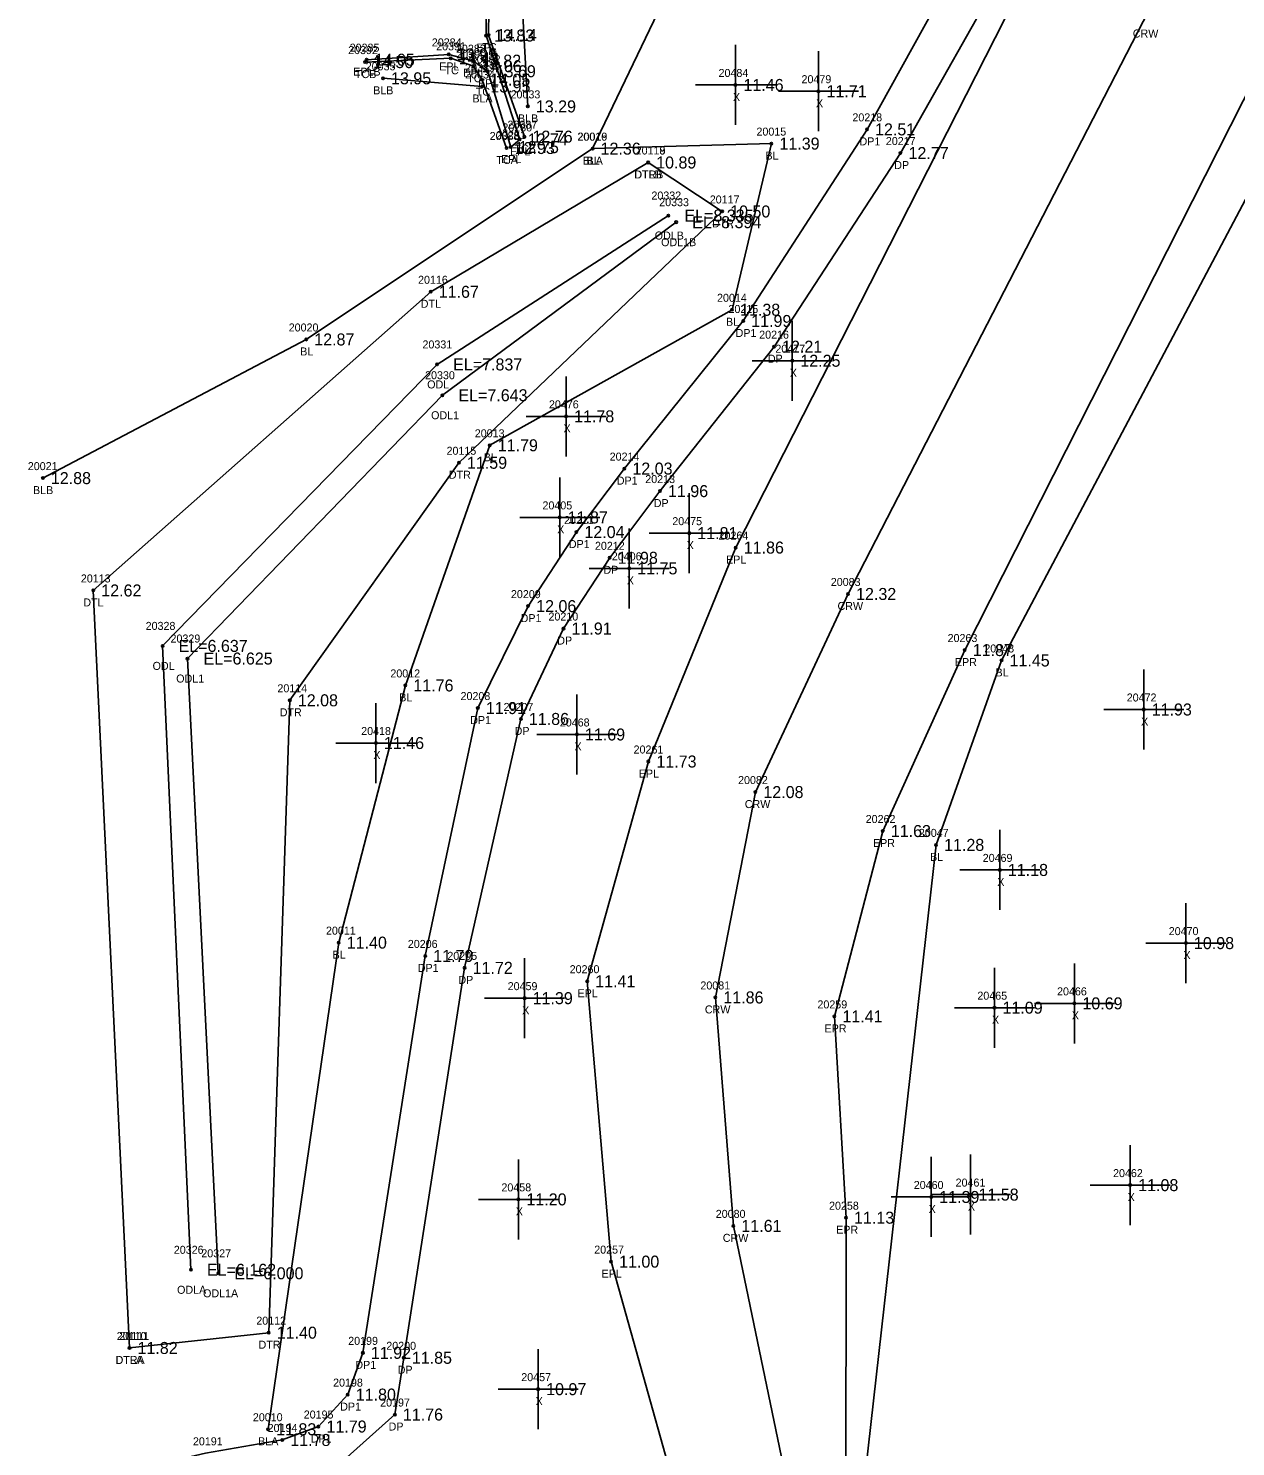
# Model space of a CAD drawing. Extents: x 2072302 to 2072980, y 127650 to 129736.
# Drawn here: x 2072687.3 to 2072838.2, y 128354.3 to 128531.6 of the extents above; entities that cross this region are included whole.
import ezdxf

# ---------------------------------------------------------------- set-up
doc = ezdxf.new("R2010")
doc.units = 0
for name, color, linetype in [('RD_DTM_BkLn1', 7, 'Continuous'), ('RD_DTM_BkLn2', 7, 'Continuous'), ('RD_DTM_BkLn_txCode', 7, 'Continuous'), ('RD_EX_Conc_txCode', 7, 'Continuous'), ('RD_EX_Driveway', 7, 'Continuous'), ('RD_EX_Driveway_txCode', 7, 'Continuous'), ('RD_EX_H2O', 7, 'Continuous'), ('RD_EX_H2O_txCode', 7, 'Continuous'), ('RD_EX_Misc', 7, 'Continuous'), ('RD_EX_Misc_txCode', 7, 'Continuous'), ('RD_EX_Road', 7, 'Continuous'), ('RD_EX_Road_txCode', 7, 'Continuous'), ('RD_EX_TX_Conc_ELEV', 7, 'Continuous'), ('RD_EX_TX_Driveway_ELEV', 7, 'Continuous'), ('RD_EX_TX_H2O_ELEV', 7, 'Continuous'), ('RD_EX_TX_Misc_ELEV', 7, 'Continuous'), ('RD_EX_TX_Road_ELEV', 7, 'Continuous'), ('RD_HC_Survey_ELEV', 7, 'Continuous'), ('RD_HC_Survey_txCode', 7, 'Continuous'), ('RD_SMD_Locator', 7, 'Continuous')]:
    doc.layers.add(name, color=color, linetype=linetype)

msp = doc.modelspace()

# ---------------------------------------------------------------- linework, layer by layer
at = {"layer": 'RD_DTM_BkLn1'}
for p, q in [((2072748.82, 128537.75), (2072749.69, 128521.83)), ((2072744, 128524.32), (2072731.59, 128525.34))]:
    msp.add_line(p, q, dxfattribs=at)
for points in [[(2072783.68, 128341.98), (2072775.38, 128381.91), (2072773.13, 128410.46), (2072778.13, 128436.13), (2072789.72, 128460.89), (2072826.62, 128532.44), (2072863.13, 128603.15), (2072886.77, 128648.23), (2072893.1, 128661.91)], [(2072717.23, 128356.49), (2072726.05, 128417.31), (2072734.38, 128449.46), (2072744.93, 128479.47), (2072775.22, 128496.41), (2072780.14, 128517.18), (2072757.78, 128516.55), (2072777.16, 128556.96), (2072786.53, 128575.88)], [(2072791.29, 128345.62), (2072800.72, 128429.53), (2072808.9, 128452.58), (2072870.32, 128568.64), (2072876.57, 128573.6), (2072916.77, 128564.68), (2072920.97, 128548.67)], [(2072757.78, 128516.55), (2072721.99, 128492.7), (2072689.07, 128475.37)]]:
    msp.add_lwpolyline(points, dxfattribs=at)
at = {"layer": 'RD_DTM_BkLn2'}
for points in [[(2072745.36, 128575.1), (2072744.79, 128530.75), (2072749.27, 128518.05)], [(2072747.04, 128516.63), (2072743.97, 128525.17), (2072742.91, 128526.85), (2072740.06, 128527.84), (2072729.35, 128527.37)]]:
    msp.add_lwpolyline(points, dxfattribs=at)
at = {"layer": 'RD_EX_Driveway'}
for points in [[(2072694.21, 128239.74), (2072695.7, 128289.15), (2072695.56, 128330.43), (2072696.37, 128337.85), (2072700.81, 128345.17), (2072711.22, 128347.96), (2072719.56, 128349.59), (2072725.15, 128351.26), (2072733.07, 128358.33), (2072734.19, 128365.42), (2072741.79, 128414.16), (2072748.82, 128445.27), (2072754.15, 128456.57), (2072759.92, 128465.41), (2072766.21, 128473.75), (2072780.47, 128491.8), (2072796.27, 128516), (2072809.9, 128540.1), (2072821.01, 128555.78)], [(2072689.37, 128239.9), (2072690.93, 128289.43), (2072690.32, 128330.24), (2072690.73, 128338.81), (2072697.63, 128350.77), (2072709.38, 128353.48), (2072719, 128355.15), (2072723.52, 128356.83), (2072727.18, 128360.82), (2072729.07, 128366.04), (2072736.87, 128415.65), (2072743.44, 128446.63), (2072749.73, 128459.37), (2072755.76, 128468.63), (2072761.76, 128476.56), (2072776.61, 128495.01), (2072792.09, 128518.96), (2072805.19, 128542.59), (2072810.66, 128554.44), (2072797.46, 128551.01)]]:
    msp.add_lwpolyline(points, dxfattribs=at)
at = {"layer": 'RD_EX_H2O'}
for points in [[(2072699.9, 128366.65), (2072695.37, 128461.33), (2072737.55, 128498.66), (2072764.73, 128514.82)], [(2072699.9, 128366.65), (2072717.3, 128368.56), (2072719.94, 128447.6), (2072741.08, 128477.29), (2072773.98, 128508.7), (2072764.73, 128514.82)], [(2072707.58, 128376.42), (2072704.03, 128454.4), (2072738.35, 128489.58), (2072767.26, 128508.19)], [(2072711, 128375.98), (2072707.15, 128452.82), (2072739.01, 128485.73), (2072768.23, 128507.36)]]:
    msp.add_lwpolyline(points, dxfattribs=at)
at = {"layer": 'RD_EX_Misc'}
for p, q in [((2072775.64, 128519.51), (2072775.64, 128529.51)), ((2072786.02, 128518.73), (2072786.02, 128528.73)), ((2072770.64, 128524.51), (2072780.64, 128524.51)), ((2072781.02, 128523.73), (2072791.02, 128523.73)), ((2072782.75, 128485.04), (2072782.75, 128495.04)), ((2072777.75, 128490.04), (2072787.75, 128490.04)), ((2072754.47, 128478.09), (2072754.47, 128488.09)), ((2072749.47, 128483.09), (2072759.47, 128483.09)), ((2072753.67, 128465.46), (2072753.67, 128475.46)), ((2072769.87, 128463.49), (2072769.87, 128473.49)), ((2072748.67, 128470.46), (2072758.67, 128470.46)), ((2072762.37, 128459.09), (2072762.37, 128469.09)), ((2072764.87, 128468.49), (2072774.87, 128468.49)), ((2072757.37, 128464.09), (2072767.37, 128464.09)), ((2072826.67, 128441.45), (2072826.67, 128451.45)), ((2072755.83, 128438.33), (2072755.83, 128448.33)), ((2072730.7, 128437.26), (2072730.7, 128447.26)), ((2072821.67, 128446.45), (2072831.67, 128446.45)), ((2072750.83, 128443.33), (2072760.83, 128443.33)), ((2072725.7, 128442.26), (2072735.7, 128442.26)), ((2072808.69, 128421.4), (2072808.69, 128431.4)), ((2072803.69, 128426.4), (2072813.69, 128426.4)), ((2072831.95, 128412.25), (2072831.95, 128422.25)), ((2072826.95, 128417.25), (2072836.95, 128417.25)), ((2072749.29, 128405.37), (2072749.29, 128415.37)), ((2072818.01, 128404.72), (2072818.01, 128414.72)), ((2072808.02, 128404.18), (2072808.02, 128414.18)), ((2072744.29, 128410.37), (2072754.29, 128410.37)), ((2072803.02, 128409.18), (2072813.02, 128409.18)), ((2072813.01, 128409.72), (2072823.01, 128409.72)), ((2072824.98, 128382), (2072824.98, 128392)), ((2072748.51, 128380.22), (2072748.51, 128390.22)), ((2072800.11, 128380.52), (2072800.11, 128390.52)), ((2072805.02, 128380.82), (2072805.02, 128390.82)), ((2072819.98, 128387), (2072829.98, 128387)), ((2072743.51, 128385.22), (2072753.51, 128385.22)), ((2072795.11, 128385.52), (2072805.11, 128385.52)), ((2072800.02, 128385.82), (2072810.02, 128385.82)), ((2072750.98, 128356.5), (2072750.98, 128366.5)), ((2072745.98, 128361.5), (2072755.98, 128361.5))]:
    msp.add_line(p, q, dxfattribs=at)
at = {"layer": 'RD_EX_Road'}
for points in [[(2072789.45, 128345.69), (2072789.46, 128382.93), (2072788.01, 128408.09), (2072794.06, 128431.26), (2072804.3, 128453.88), (2072840.7, 128525.64), (2072876.68, 128596.08), (2072888.72, 128617.36), (2072893.24, 128622.62), (2072899.84, 128627.36), (2072910.72, 128631.76), (2072918.79, 128632.23), (2072935.82, 128627.02), (2072957.37, 128619.98)], [(2072744.65, 128575.04), (2072744.47, 128530.69), (2072748.67, 128517.7), (2072747.55, 128516.74), (2072744.67, 128526.22), (2072742.83, 128527.54), (2072739.81, 128528.33), (2072729.54, 128527.67)], [(2072771.5, 128336.87), (2072760.1, 128377.44), (2072757.11, 128412.49), (2072764.76, 128439.95), (2072775.68, 128466.69), (2072812.91, 128539.86)]]:
    msp.add_lwpolyline(points, dxfattribs=at)
at = {"layer": 'RD_SMD_Locator'}
for centre in [(2072744.47, 128530.69), (2072744.79, 128530.75), (2072739.81, 128528.33), (2072740.06, 128527.84), (2072729.35, 128527.37), (2072729.54, 128527.67), (2072742.83, 128527.54), (2072742.91, 128526.85), (2072744.67, 128526.22), (2072731.59, 128525.34), (2072743.97, 128525.17), (2072744, 128524.32), (2072775.64, 128524.51), (2072786.02, 128523.73), (2072749.69, 128521.83), (2072792.09, 128518.96), (2072748.67, 128517.7), (2072749.27, 128518.05), (2072780.14, 128517.18), (2072747.04, 128516.63), (2072747.55, 128516.74), (2072757.78, 128516.55), (2072757.78, 128516.55), (2072796.27, 128516), (2072764.73, 128514.82), (2072764.73, 128514.82), (2072773.98, 128508.7), (2072767.26, 128508.19), (2072768.23, 128507.36), (2072737.55, 128498.66), (2072775.22, 128496.41), (2072776.61, 128495.01), (2072721.99, 128492.7), (2072780.47, 128491.8), (2072738.35, 128489.58), (2072782.75, 128490.04), (2072739.01, 128485.73), (2072754.47, 128483.09), (2072744.93, 128479.47), (2072741.08, 128477.29), (2072761.76, 128476.56), (2072689.07, 128475.37), (2072766.21, 128473.75), (2072753.67, 128470.46), (2072755.76, 128468.63), (2072769.87, 128468.49), (2072775.68, 128466.69), (2072759.92, 128465.41), (2072762.37, 128464.09), (2072695.37, 128461.33), (2072789.72, 128460.89), (2072749.73, 128459.37), (2072754.15, 128456.57), (2072704.03, 128454.4), (2072804.3, 128453.88), (2072707.15, 128452.82), (2072808.9, 128452.58), (2072734.38, 128449.46), (2072719.94, 128447.6), (2072743.44, 128446.63), (2072826.67, 128446.45), (2072748.82, 128445.27), (2072755.83, 128443.33), (2072730.7, 128442.26), (2072764.76, 128439.95), (2072778.13, 128436.13), (2072794.06, 128431.26), (2072800.72, 128429.53), (2072808.69, 128426.4), (2072726.05, 128417.31), (2072831.95, 128417.25), (2072736.87, 128415.65), (2072741.79, 128414.16), (2072757.11, 128412.49), (2072749.29, 128410.37), (2072773.13, 128410.46), (2072808.02, 128409.18), (2072818.01, 128409.72), (2072788.01, 128408.09), (2072824.98, 128387), (2072748.51, 128385.22), (2072800.11, 128385.52), (2072805.02, 128385.82), (2072789.46, 128382.93), (2072775.38, 128381.91), (2072760.1, 128377.44), (2072707.58, 128376.42), (2072711, 128375.98), (2072717.3, 128368.56), (2072699.9, 128366.65), (2072699.9, 128366.65), (2072729.07, 128366.04), (2072734.19, 128365.42), (2072750.98, 128361.5), (2072727.18, 128360.82), (2072733.07, 128358.33), (2072717.23, 128356.49), (2072723.52, 128356.83), (2072719, 128355.15)]:
    msp.add_circle(centre, 0.15, dxfattribs=at)

# ---------------------------------------------------------------- texts
at = {"layer": 'RD_DTM_BkLn_txCode'}
for s, p in [('20035', (2072729.43, 128526.34)), ('20034', (2072741.84, 128525.32)), ('BLB', (2072730.36, 128523.34)), ('BLA', (2072742.76, 128522.32)), ('20033', (2072747.53, 128522.83)), ('BLB', (2072748.46, 128519.83)), ('20015', (2072778.27, 128518.18)), ('20016', (2072755.88, 128517.55)), ('20019', (2072755.91, 128517.55)), ('BLA', (2072756.54, 128514.55)), ('BL', (2072757.03, 128514.55)), ('BL', (2072779.39, 128515.18)), ('20014', (2072773.34, 128497.41)), ('20020', (2072719.8, 128493.7)), ('BL', (2072774.46, 128494.41)), ('BL', (2072721.24, 128490.7)), ('20013', (2072743.06, 128480.47)), ('BL', (2072744.18, 128477.47)), ('20021', (2072687.19, 128476.37)), ('BLB', (2072687.84, 128473.37)), ('20048', (2072806.75, 128453.58)), ('20012', (2072732.51, 128450.46)), ('BL', (2072808.15, 128450.58)), ('BL', (2072733.62, 128447.46)), ('20047', (2072798.57, 128430.53)), ('BL', (2072799.97, 128427.53)), ('20011', (2072724.46, 128418.31)), ('BL', (2072725.29, 128415.31)), ('20010', (2072715.32, 128357.49)), ('BLA', (2072715.98, 128354.49))]:
    msp.add_text(s, height=1, dxfattribs=at).set_placement(p)
at = {"layer": 'RD_EX_Conc_txCode'}
for s, p in [('20391', (2072738.23, 128528.84)), ('TC', (2072744, 128528.75)), ('20392', (2072727.23, 128528.37)), ('20390', (2072740.75, 128527.85)), ('TCB', (2072728.08, 128525.37)), ('TC', (2072739.27, 128525.84)), ('20389', (2072741.85, 128526.17)), ('TC', (2072742.11, 128524.85)), ('TC', (2072743.18, 128523.17)), ('20387', (2072747.15, 128519.05)), ('20388', (2072744.92, 128517.63)), ('TCA', (2072745.76, 128514.63)), ('TCB', (2072748.01, 128516.05))]:
    msp.add_text(s, height=1, dxfattribs=at).set_placement(p)
at = {"layer": 'RD_EX_Driveway_txCode'}
for s, p in [('20218', (2072790.26, 128519.96)), ('DP1', (2072791.15, 128516.96)), ('20217', (2072794.44, 128517)), ('DP', (2072795.49, 128514)), ('20215', (2072774.77, 128496.01)), ('DP1', (2072775.66, 128493.01)), ('20216', (2072778.61, 128492.8)), ('DP', (2072779.69, 128489.8)), ('20214', (2072759.92, 128477.56)), ('DP1', (2072760.81, 128474.56)), ('20213', (2072764.37, 128474.75)), ('DP', (2072765.43, 128471.75)), ('20211', (2072754.21, 128469.63)), ('DP1', (2072754.82, 128466.63)), ('20212', (2072758.08, 128466.41)), ('DP', (2072759.14, 128463.41)), ('20209', (2072747.58, 128460.37)), ('DP1', (2072748.79, 128457.37)), ('20210', (2072752.27, 128457.57)), ('DP', (2072753.37, 128454.57)), ('20208', (2072741.28, 128447.63)), ('20207', (2072746.66, 128446.27)), ('DP1', (2072742.49, 128444.63)), ('DP', (2072748.04, 128443.27)), ('20206', (2072734.69, 128416.65)), ('DP1', (2072735.93, 128413.65)), ('20205', (2072739.63, 128415.16)), ('DP', (2072741.01, 128412.16)), ('20199', (2072727.24, 128367.04)), ('20200', (2072732, 128366.42)), ('DP1', (2072728.13, 128364.04)), ('DP', (2072733.42, 128363.42)), ('20198', (2072725.35, 128361.82)), ('DP1', (2072726.24, 128358.82)), ('20197', (2072731.23, 128359.33)), ('20195', (2072721.68, 128357.83)), ('20194', (2072717.17, 128356.15)), ('DP', (2072732.29, 128356.33)), ('20191', (2072707.83, 128354.48)), ('DP1', (2072722.57, 128354.83))]:
    msp.add_text(s, height=1, dxfattribs=at).set_placement(p)
at = {"layer": 'RD_EX_H2O_txCode'}
for s, p in [('20118', (2072763.17, 128515.82)), ('20119', (2072763.17, 128515.82)), ('DTRB', (2072762.98, 128512.82)), ('DTLB', (2072763.01, 128512.82)), ('20332', (2072765.14, 128510.19)), ('20333', (2072766.11, 128509.36)), ('20117', (2072772.43, 128509.7)), ('DTR', (2072772.71, 128506.7)), ('ODLB', (2072765.55, 128505.19)), ('ODL1B', (2072766.35, 128504.36)), ('20116', (2072735.97, 128499.66)), ('DTL', (2072736.3, 128496.66)), ('20331', (2072736.52, 128491.58)), ('20330', (2072736.85, 128487.73)), ('ODL', (2072737.11, 128486.58)), ('ODL1', (2072737.6, 128482.73)), ('20115', (2072739.53, 128478.29)), ('DTR', (2072739.82, 128475.29)), ('20113', (2072693.82, 128462.33)), ('DTL', (2072694.13, 128459.33)), ('20328', (2072701.92, 128456.4)), ('20329', (2072705.03, 128454.82)), ('ODL', (2072702.79, 128451.4)), ('ODL1', (2072705.74, 128449.82)), ('20114', (2072718.39, 128448.6)), ('DTR', (2072718.68, 128445.6)), ('20326', (2072705.44, 128378.42)), ('20327', (2072708.88, 128377.98)), ('ODLA', (2072705.85, 128373.42)), ('ODL1A', (2072709.1, 128372.98)), ('20112', (2072715.75, 128369.56)), ('20110', (2072698.31, 128367.65)), ('20111', (2072698.63, 128367.65)), ('DTR', (2072716.03, 128366.56)), ('DTRA', (2072698.15, 128364.65)), ('DTLA', (2072698.17, 128364.65))]:
    msp.add_text(s, height=1, dxfattribs=at).set_placement(p)
at = {"layer": 'RD_EX_Misc_txCode'}
for s, p in [('20484', (2072773.53, 128525.51)), ('20479', (2072783.9, 128524.73)), ('X', (2072775.33, 128522.51)), ('X', (2072785.71, 128521.73)), ('20477', (2072780.63, 128491.04)), ('X', (2072782.43, 128488.04)), ('20476', (2072752.33, 128484.09)), ('X', (2072754.15, 128481.09)), ('20405', (2072751.52, 128471.46)), ('X', (2072753.36, 128468.46)), ('20475', (2072767.75, 128469.49)), ('20406', (2072760.19, 128465.09)), ('X', (2072769.55, 128466.49)), ('X', (2072762.06, 128462.09)), ('20472', (2072824.55, 128447.45)), ('20468', (2072753.69, 128444.33)), ('X', (2072826.35, 128444.45)), ('20418', (2072728.86, 128443.26)), ('X', (2072730.38, 128440.26)), ('X', (2072755.52, 128441.33)), ('20469', (2072806.55, 128427.4)), ('X', (2072808.37, 128424.4)), ('20470', (2072829.8, 128418.25)), ('X', (2072831.64, 128415.25)), ('20459', (2072747.17, 128411.37)), ('20465', (2072805.88, 128410.18)), ('20466', (2072815.84, 128410.72)), ('X', (2072748.98, 128408.37)), ('X', (2072807.71, 128407.18)), ('X', (2072817.69, 128407.72)), ('20462', (2072822.84, 128388)), ('20458', (2072746.39, 128386.22)), ('20460', (2072797.93, 128386.52)), ('20461', (2072803.16, 128386.82)), ('X', (2072799.79, 128383.52)), ('X', (2072804.7, 128383.82)), ('X', (2072824.67, 128385)), ('X', (2072748.19, 128383.22)), ('20457', (2072748.87, 128362.5)), ('X', (2072750.67, 128359.5))]:
    msp.add_text(s, height=1, dxfattribs=at).set_placement(p)
at = {"layer": 'RD_EX_Road_txCode'}
for s, p in [('20284', (2072737.69, 128529.33)), ('20285', (2072727.42, 128528.67)), ('20283', (2072740.71, 128528.54)), ('20282', (2072742.56, 128527.22)), ('EPL', (2072743.26, 128528.69)), ('EPLB', (2072727.86, 128525.67)), ('EPL', (2072738.61, 128526.33)), ('EPL', (2072741.62, 128525.54)), ('EPL', (2072743.47, 128524.22)), ('20280', (2072746.51, 128518.7)), ('20281', (2072745.72, 128517.74)), ('EPL', (2072746.35, 128514.74)), ('EPL', (2072747.47, 128515.7)), ('20264', (2072773.53, 128467.69)), ('EPL', (2072774.47, 128464.69)), ('20263', (2072802.16, 128454.88)), ('EPR', (2072803.07, 128451.88)), ('20261', (2072762.91, 128440.95)), ('EPL', (2072763.56, 128437.95)), ('20262', (2072791.92, 128432.26)), ('EPR', (2072792.83, 128429.26)), ('20260', (2072754.92, 128413.49)), ('EPL', (2072755.9, 128410.49)), ('20259', (2072785.89, 128409.09)), ('EPR', (2072786.78, 128406.09)), ('20258', (2072787.34, 128383.93)), ('EPR', (2072788.23, 128380.93)), ('20257', (2072757.99, 128378.44)), ('EPL', (2072758.9, 128375.44))]:
    msp.add_text(s, height=1, dxfattribs=at).set_placement(p)
at = {"layer": 'RD_EX_TX_Conc_ELEV'}
for s, p in [('14.14', (2072745.79, 128530)), ('14.50', (2072730.35, 128526.62)), ('14.43', (2072741.06, 128527.09)), ('14.06', (2072743.91, 128526.1)), ('14.05', (2072744.97, 128524.42)), ('12.93', (2072748.04, 128515.88)), ('12.76', (2072750.27, 128517.3))]:
    msp.add_text(s, height=1.5, dxfattribs=at).set_placement(p)
at = {"layer": 'RD_EX_TX_Driveway_ELEV'}
for s, p in [('12.51', (2072793.09, 128518.21)), ('12.77', (2072797.27, 128515.25)), ('11.99', (2072777.61, 128494.26)), ('12.21', (2072781.47, 128491.05)), ('12.03', (2072762.76, 128475.81)), ('11.96', (2072767.21, 128473)), ('12.04', (2072756.76, 128467.88)), ('11.98', (2072760.92, 128464.66)), ('12.06', (2072750.73, 128458.62)), ('11.91', (2072755.15, 128455.82)), ('11.91', (2072744.44, 128445.88)), ('11.86', (2072749.82, 128444.52)), ('11.79', (2072737.87, 128414.9)), ('11.72', (2072742.79, 128413.41)), ('11.92', (2072730.07, 128365.29)), ('11.85', (2072735.19, 128364.67)), ('11.80', (2072728.18, 128360.07)), ('11.76', (2072734.07, 128357.58)), ('11.79', (2072724.52, 128356.08)), ('11.78', (2072720, 128354.4))]:
    msp.add_text(s, height=1.5, dxfattribs=at).set_placement(p)
at = {"layer": 'RD_EX_TX_H2O_ELEV'}
for s, p in [('10.89', (2072765.73, 128514.07)), ('10.89', (2072765.73, 128514.07)), ('EL=8.335', (2072769.26, 128507.44)), ('10.50', (2072774.98, 128507.95)), ('EL=8.394', (2072770.23, 128506.61)), ('11.67', (2072738.55, 128497.91)), ('EL=7.837', (2072740.35, 128488.83)), ('EL=7.643', (2072741.01, 128484.98)), ('11.59', (2072742.08, 128476.54)), ('12.62', (2072696.37, 128460.58)), ('EL=6.637', (2072706.03, 128453.65)), ('EL=6.625', (2072709.15, 128452.07)), ('12.08', (2072720.94, 128446.85)), ('EL=6.162', (2072709.58, 128375.67)), ('EL=6.000', (2072713, 128375.23)), ('11.40', (2072718.3, 128367.81)), ('11.82', (2072700.9, 128365.9)), ('11.82', (2072700.9, 128365.9))]:
    msp.add_text(s, height=1.5, dxfattribs=at).set_placement(p)
at = {"layer": 'RD_EX_TX_Misc_ELEV'}
for s, p in [('13.95', (2072732.59, 128524.59)), ('13.95', (2072745, 128523.57)), ('11.46', (2072776.64, 128523.76)), ('11.71', (2072787.02, 128522.98)), ('13.29', (2072750.69, 128521.08)), ('12.36', (2072758.78, 128515.8)), ('12.36', (2072758.78, 128515.8)), ('11.39', (2072781.14, 128516.43)), ('11.38', (2072776.22, 128495.66)), ('12.87', (2072722.99, 128491.95)), ('12.25', (2072783.75, 128489.29)), ('11.78', (2072755.47, 128482.34)), ('11.79', (2072745.93, 128478.72)), ('12.88', (2072690.07, 128474.62)), ('11.87', (2072754.67, 128469.71)), ('11.81', (2072770.87, 128467.74)), ('11.75', (2072763.37, 128463.34)), ('11.45', (2072809.9, 128451.83)), ('11.76', (2072735.38, 128448.71)), ('11.93', (2072827.67, 128445.7)), ('11.46', (2072731.7, 128441.51)), ('11.69', (2072756.83, 128442.58)), ('11.28', (2072801.72, 128428.78)), ('11.18', (2072809.69, 128425.65)), ('11.40', (2072727.05, 128416.56)), ('10.98', (2072832.95, 128416.5)), ('11.39', (2072750.29, 128409.62)), ('11.09', (2072809.02, 128408.43)), ('10.69', (2072819.01, 128408.97)), ('11.39', (2072801.11, 128384.77)), ('11.58', (2072806.02, 128385.07)), ('11.08', (2072825.98, 128386.25)), ('11.20', (2072749.51, 128384.47)), ('10.97', (2072751.98, 128360.75)), ('11.83', (2072718.23, 128355.74))]:
    msp.add_text(s, height=1.5, dxfattribs=at).set_placement(p)
at = {"layer": 'RD_EX_TX_Road_ELEV'}
for s, p in [('13.83', (2072745.47, 128529.94)), ('14.05', (2072730.54, 128526.92)), ('13.95', (2072740.81, 128527.58)), ('13.82', (2072743.83, 128526.79)), ('13.69', (2072745.67, 128525.47)), ('12.75', (2072748.55, 128515.99)), ('12.74', (2072749.67, 128516.95)), ('11.86', (2072776.68, 128465.94)), ('11.87', (2072805.3, 128453.13)), ('11.73', (2072765.76, 128439.2)), ('11.63', (2072795.06, 128430.51)), ('11.41', (2072758.11, 128411.74)), ('11.41', (2072789.01, 128407.34)), ('11.13', (2072790.46, 128382.18)), ('11.00', (2072761.1, 128376.69))]:
    msp.add_text(s, height=1.5, dxfattribs=at).set_placement(p)
at = {"layer": 'RD_HC_Survey_ELEV'}
for s, p in [('12.32', (2072790.72, 128460.14)), ('12.08', (2072779.13, 128435.38)), ('11.86', (2072774.13, 128409.71)), ('11.61', (2072776.38, 128381.16))]:
    msp.add_text(s, height=1.5, dxfattribs=at).set_placement(p)
at = {"layer": 'RD_HC_Survey_txCode'}
for s, p in [('CRW', (2072825.31, 128530.44)), ('20083', (2072787.56, 128461.89)), ('CRW', (2072788.4, 128458.89)), ('20082', (2072775.97, 128437.13)), ('CRW', (2072776.81, 128434.13)), ('20081', (2072771.26, 128411.46)), ('CRW', (2072771.82, 128408.46)), ('20080', (2072773.18, 128382.91)), ('CRW', (2072774.06, 128379.91))]:
    msp.add_text(s, height=1, dxfattribs=at).set_placement(p)

doc.saveas('drawing.dxf')
